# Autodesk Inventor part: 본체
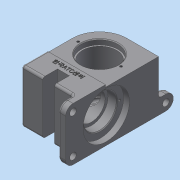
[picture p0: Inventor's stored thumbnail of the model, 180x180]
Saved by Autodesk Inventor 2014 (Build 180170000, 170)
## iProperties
Created: 2023-09
Part Number: 본체
Material: 일반
Document SubType Name: Modeling
Designer: dg
Density: 1 g/cm^3
Appearance: 기본값
Author: dg
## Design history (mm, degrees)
sketch "스케치1"
  geometry: L1 (43, 71)-(43, -35); L2 (43, -35)-(-37, -35); L3 (-37, -35)-(-37, 34); L4 (0, 71)-(43, 71); A1 r 37 centre (0, 34) between (0, 71) and (-37, 34); 1 further point
  constraints: 8 end point, 2 perpendicular, 2 point on circle, 1 centre point, 1 parallel, 1 tangent, 1 vertical, 1 vertical alignment
  dimensions: "d0" = 106 distance between parallel lines of L2 L4; "d2" = 80 distance between parallel lines of L3 L1; "d37" = 37 radius of A1; "d39" = 35 distance from line of point (0, 0) L2; "d40" = 34 distance of point (0, 0) A1.centre
extrude "돌출1" new body sketch "스케치1" stored distance "d5" = 72; taper "d6" = 0 deg
sketch "스케치2"
  geometry: L1 (72, 106)-(72, 0) reference; L2 (0, 0)-(72, 0); L3 (72, 0)-(72, -20); L4 (72, -20)-(0, -20); L5 (0, -20)-(0, 0); 3 further points
  constraints: 8 end point, 2 midpoint, 2 parallel, 1 horizontal, 1 perpendicular, 1 vertical alignment
  dimensions: "d7" = 20 distance of L4.end L2.start
extrude "돌출2" join sketch "스케치2" distance "d8" = 10; taper "d9" = 0 deg
sketch "스케치3"
  geometry: 1 further point
hole "구멍1" sketch "스케치3" at (-36, 35) diameter "d10" = 45; stored, may be unused: countersink angle "d14" = 90 deg, drill point angle "d16" = 0 deg; dims "d11" = 6, "d12" = 63, "d13" = 3, "d15" = 15
sketch "스케치4"
  geometry: 1 further point
hole "구멍2" sketch "스케치4" at (36, -71) diameter "d17" = 45; stored, may be unused: countersink angle "d21" = 90 deg, drill point angle "d23" = 0 deg; dims "d18" = 6, "d19" = 63, "d20" = 8, "d22" = 20
sketch "스케치5"
  geometry: C1 r 22.5 at (0, 0) reference
hole "구멍3" sketch "스케치5" at (0, 0) diameter "d24" = 37; stored, may be unused: countersink angle "d28" = 90 deg, drill point angle "d30" = 0 deg; dims "d25" = 6, "d26" = 63, "d27" = 8, "d29" = 20
node "작업 평면1"
sketch "스케치6"
  geometry: L1 (-37, 0)-(33, 0) reference; L2 (-37, 4.5)-(-37, 67.5) reference; L3 (-37, 0)-(-37, 72) reference; L4 (43, 0)-(33, 0) reference; L5 (43, 0)-(43, 72) reference; L6 (43, 0)-(-37, 0); L7 (-37, 0)-(-37, 3); L8 (-37, 3)-(43, 3); L9 (43, 3)-(43, 0); 1 further point
  constraints: 8 end point, 2 parallel, 1 horizontal, 1 perpendicular, 1 point on line
  dimensions: "d32" = 3 distance of L8.end L4.start
extrude "돌출3" cut sketch "스케치6" distance "d33" = 72; taper "d34" = 0 deg
sketch "스케치7"
  geometry: A1 r 37 centre (37, 35) between (37, 72) and (0, 35) reference; 1 further point
hole "구멍4" sketch "스케치7" at (37, 35) diameter "d41" = 46; stored, may be unused: countersink angle "d45" = 90 deg, drill point angle "d47" = 0 deg; dims "d42" = 6, "d43" = 50, "d44" = 7, "d46" = 47
sketch "스케치8"
  geometry: A1 r 23 centre (0, 0) between (7.007, -21.907) and (-7.007, -21.907) reference; 1 further point
hole "구멍5" sketch "스케치8" at (0, 0) diameter "d48" = 31; stored, may be unused: countersink angle "d52" = 90 deg, drill point angle "d54" = 0 deg; dims "d49" = 6, "d50" = 35, "d51" = 15, "d53" = 19
sketch "스케치9"
  geometry: L1 (0, 0)-(72, 0) reference; L2 (72, 126)-(3, 126) reference; L3 (52, 126)-(52, 136); L4 (72, 136)-(72, 126); A1 r 10 centre (62, 136) between (72, 136) and (52, 136); 1 further point
  constraints: 4 end point, 3 point on circle, 2 tangent, 1 centre point, 1 parallel, 1 perpendicular, 1 point on line
  dimensions: "d55" = 20 distance between parallel lines of L4 L3; "d56" = 136 distance from line of L1 A1.centre
extrude "돌출4" join sketch "스케치9" distance "d57" = 10; taper "d58" = 0 deg
sketch "스케치10"
  geometry: A1 r 10 centre (-62, 136) between (-52, 136) and (-72, 136) reference; 1 further point
hole "구멍6" sketch "스케치10" at (-62, 136) diameter "d59" = 9; stored, may be unused: countersink angle "d63" = 90 deg, drill point angle "d65" = 0 deg; dims "d60" = 6, "d61" = 35, "d62" = 15, "d64" = 19
fillet "모깎기1" dims "d66" = 10
sketch "스케치11"
  geometry: A1 r 10 centre (-10, -10) between (-10, -20) and (0, -10) reference; A2 r 10 centre (-62, -10) between (-72, -10) and (-62, -20) reference; 1 further point
hole "구멍7" sketch "스케치11" at (-62, -10), (-10, -10) diameter "d67" = 9; stored, may be unused: countersink angle "d71" = 90 deg, drill point angle "d73" = 0 deg; dims "d68" = 6, "d69" = 35, "d70" = 15, "d72" = 19
fillet "모깎기2" dims "d74" = 3
fillet "모깎기3" dims "d75" = 0.3
fillet "모깎기4" dims "d76" = 3
fillet "모깎기5" dims "d77" = 3
fillet "모깎기8" dims "d80" = 3
fillet "모깎기9" dims "d81" = 3
fillet "모깎기10" dims "d82" = 3
sketch "스케치12"
  geometry: L1 (-34, -35)-(30, -35) reference; 2 further points
  constraints: 1 vertical alignment, 1 other
  dimensions: "d83" = 27 distance from line of point (0, -8) L1
feature "엠보싱1" sketch "스케치12" dims "d0" = 106, "d2" = 80, "d16" = 0, "d37" = 37, "d39" = 35, "d40" = 34, "d84" = 0.5, "d85" = 0
sketch "스케치13"
  geometry: L1 (-8, -15)-(8, -15); L2 (8, -15)-(8, -35); L3 (8, -35)-(-8, -35); L4 (-8, -35)-(-8, -15); L5 (-34, -35)-(30, -35) reference; 4 further points
  constraints: 8 end point, 3 midpoint, 2 parallel, 1 horizontal, 1 horizontal alignment, 1 perpendicular, 1 vertical alignment
  dimensions: "d86" = 16 distance of L2.end L3.end; "d87" = 20 distance between parallel lines of L5 L1
extrude "돌출5" cut sketch "스케치13" stored distance "d88" = 10; taper "d89" = 0 deg
sketch "스케치14"
  geometry: C1 r 31.5 at (0, 0) reference; 2 further points
  constraints: 2 vertical alignment
  dimensions: "d93" = 26 distance of point (0, 26) C1.centre; "d94" = 52 distance of point (0, -26) point (0, 26)
hole "구멍8" sketch "스케치14" at (0, 26), (0, -26) diameter "d95" = 3.242; stored, may be unused: countersink angle "d99" = 90 deg, drill point angle "d101" = 118 deg; dims "d96" = 8, "d97" = 35, "d98" = 15, "d100" = 10
sketch "스케치15"
  geometry: C1 r 31.5 at (0, 0) reference; 2 further points
  constraints: 2 vertical alignment
  dimensions: "d102" = 26 distance of C1.centre point (0, 26); "d103" = 52 distance of point (0, -26) point (0, 26)
hole "구멍9" sketch "스케치15" at (0, 26), (0, -26) diameter "d104" = 3.242; stored, may be unused: countersink angle "d108" = 90 deg, drill point angle "d110" = 118 deg; dims "d105" = 8, "d106" = 35, "d107" = 15, "d109" = 10
sketch "스케치16"
  geometry: C1 r 25 at (0, -37) reference; 3 further points
  constraints: 2 horizontal alignment
  dimensions: "d111" = 58 distance of point (29, -37) point (-29, -37); "d112" = 29 distance of point (29, -37) C1.centre
hole "구멍10" sketch "스케치16" at (-29, -37), (29, -37) diameter "d113" = 3.242; stored, may be unused: countersink angle "d117" = 90 deg, drill point angle "d119" = 118 deg; dims "d114" = 8, "d115" = 35, "d116" = 15, "d118" = 10
chamfer "모따기2" distance "d120" = 1; stored, may be unused: second distance "d121" = 2, angle "d122" = 45 deg
chamfer "모따기3" distance "d123" = 1; stored, may be unused: second distance "d124" = 2, angle "d125" = 45 deg
chamfer "모따기4" distance "d126" = 1; stored, may be unused: second distance "d127" = 2, angle "d128" = 45 deg
node "솔리드1"
other parameters: "d31" = -72
